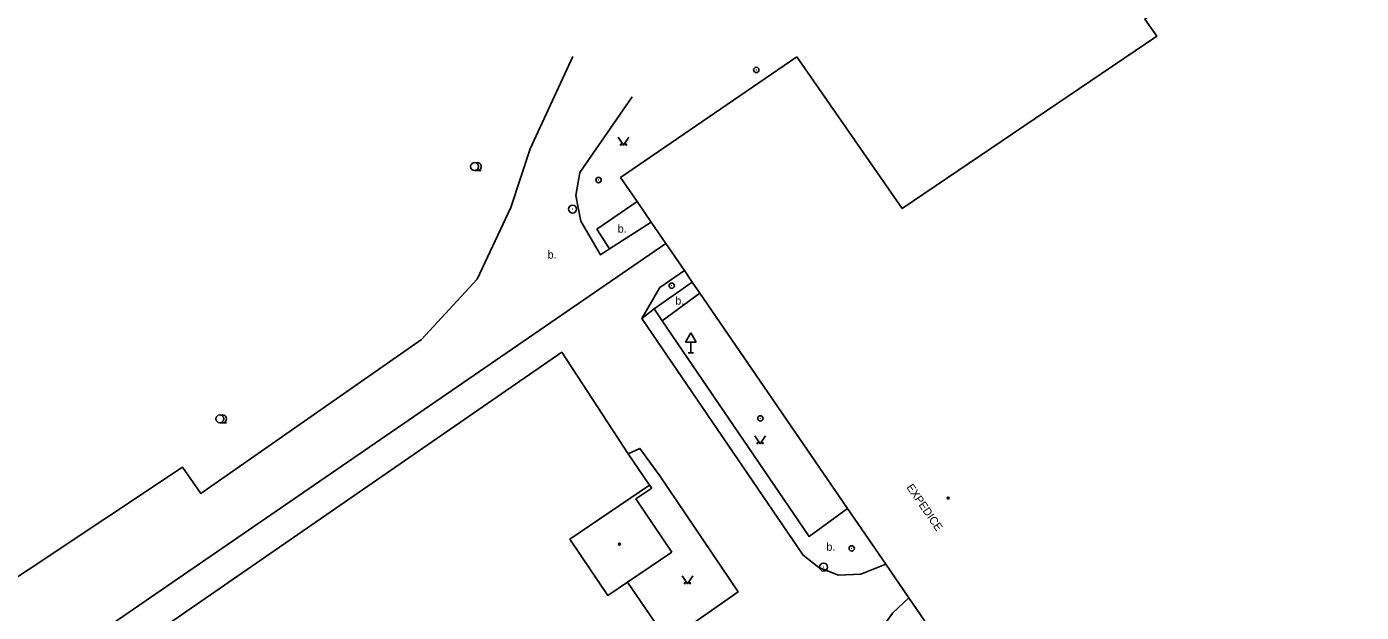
# Model space of a CAD drawing. Extents: x -545714 to -535419, y -1201788 to -1194297.
# Drawn here: x -545279.7 to -545154.6, y -1194807.5 to -1194752.6 of the extents above; entities that cross this region are included whole.
import ezdxf

# ---------------------------------------------------------------- set-up
doc = ezdxf.new("R2010")
doc.units = 0
for name, color, linetype in [('Vrstva 1', 7, 'Continuous'), ('Vrstva 10', 7, 'Continuous'), ('Vrstva 11', 7, 'Continuous'), ('Vrstva 15', 7, 'Continuous'), ('Vrstva 3', 7, 'Continuous'), ('Vrstva 4', 7, 'Continuous'), ('Vrstva 5', 7, 'Continuous'), ('Vrstva 9', 7, 'Continuous')]:
    doc.layers.add(name, color=color, linetype=linetype)

msp = doc.modelspace()

# ---------------------------------------------------------------- linework, layer by layer
at = {"layer": 'Vrstva 1'}
for centre, radius in [((-545228.49, -1194769.7), 0.375), ((-545228.49, -1194769.7), 0.0005), ((-545204.97, -1194803.28), 0.375), ((-545204.97, -1194803.28), 0.0005)]:
    msp.add_circle(centre, radius, dxfattribs=at)
at = {"layer": 'Vrstva 10'}
for p, q in [((-545217.41, -1194781.32), (-545217.91, -1194782.19)), ((-545217.41, -1194781.32), (-545216.91, -1194782.19)), ((-545217.91, -1194782.19), (-545216.91, -1194782.19)), ((-545217.41, -1194783.19), (-545217.41, -1194782.19)), ((-545217.66, -1194783.19), (-545217.16, -1194783.19))]:
    msp.add_line(p, q, dxfattribs=at)
for points in [[(-545219.75, -1194772.93), (-545277.34, -1194812.51), (-545286.35, -1194818.39), (-545298.69, -1194825.48), (-545311.57, -1194831.65), (-545328.37, -1194838.02), (-545342.45, -1194842.1)], [(-545216.56, -1194777.58), (-545220.1, -1194780.17), (-545220.84, -1194779.07), (-545217.27, -1194776.54)], [(-545221.27, -1194795.6), (-545223.27, -1194792.64), (-545229.51, -1194783.12), (-545266.38, -1194808.61), (-545303.95, -1194834.27), (-545301.94, -1194837.11)], [(-545199.15, -1194840.08), (-545223.35, -1194804.69)]]:
    msp.add_lwpolyline(points, dxfattribs=at)
for centre, radius in [((-545211.27, -1194756.65), 0.25), ((-545211.27, -1194756.65), 0.0005), ((-545226.06, -1194766.98), 0.25), ((-545226.06, -1194766.98), 0.0005), ((-545219.2, -1194776.89), 0.25), ((-545219.2, -1194776.89), 0.0005), ((-545210.89, -1194789.33), 0.25), ((-545210.89, -1194789.33), 0.0005), ((-545202.33, -1194801.52), 0.25), ((-545202.33, -1194801.52), 0.0005)]:
    msp.add_circle(centre, radius, dxfattribs=at)
at = {"layer": 'Vrstva 11'}
for points in [[(-545232.48, -1194764.06), (-545228.47, -1194755.38)], [(-545222.92, -1194759.17), (-545227.82, -1194766.27), (-545228.2, -1194768.42), (-545227.71, -1194770.84), (-545225.88, -1194773.98), (-545225.04, -1194773.44), (-545221.12, -1194770.93)], [(-545294.04, -1194813.16), (-545265.06, -1194793.9), (-545263.35, -1194796.36), (-545242.67, -1194781.94), (-545237.45, -1194776.27), (-545234.28, -1194769.55), (-545232.48, -1194764.06)], [(-545222.44, -1194769), (-545226.23, -1194771.59)], [(-545225.04, -1194773.44), (-545226.23, -1194771.59)], [(-545218.01, -1194775.46), (-545220.31, -1194777.04)], [(-545220.31, -1194777.04), (-545222, -1194779.96), (-545206.89, -1194802.17), (-545205.4, -1194803.31), (-545203.56, -1194804.02), (-545201.48, -1194803.93), (-545199.14, -1194802.99)], [(-545222, -1194779.96), (-545220.84, -1194779.07)], [(-545220.1, -1194780.17), (-545206.33, -1194800.4), (-545202.71, -1194797.78)], [(-545199.26, -1194838.53), (-545218.99, -1194809.8), (-545212.98, -1194805.59), (-545220.33, -1194794.71), (-545222.18, -1194792.15), (-545223.27, -1194792.64)], [(-545196.97, -1194806.15), (-545198.51, -1194807.6), (-545199.47, -1194808.96), (-545199.75, -1194811.2), (-545199.03, -1194813.48), (-545178.86, -1194843.1), (-545175.81, -1194842.57), (-545164.95, -1194835.42), (-545163.84, -1194833.77), (-545163.52, -1194831.74), (-545164.19, -1194829.82), (-545170.36, -1194820.85)]]:
    msp.add_lwpolyline(points, dxfattribs=at)
at = {"layer": 'Vrstva 3'}
for p, q in [((-545237.68, -1194766.08), (-545237.06, -1194766.08)), ((-545261.56, -1194789.75), (-545260.94, -1194789.75))]:
    msp.add_line(p, q, dxfattribs=at)
for points in [[(-545224.21, -1194762.96), (-545223.71, -1194763.71), (-545223.21, -1194762.96)], [(-545211.41, -1194790.96), (-545210.91, -1194791.71), (-545210.41, -1194790.96)], [(-545218.22, -1194804.09), (-545217.72, -1194804.84), (-545217.22, -1194804.09)]]:
    msp.add_lwpolyline(points, dxfattribs=at)
for centre, radius in [((-545223.96, -1194763.66), 0.05), ((-545223.46, -1194763.66), 0.05), ((-545237.68, -1194765.71), 0.375), ((-545261.56, -1194789.37), 0.375), ((-545211.16, -1194791.66), 0.05), ((-545210.66, -1194791.66), 0.05), ((-545217.97, -1194804.79), 0.05), ((-545217.47, -1194804.79), 0.05)]:
    msp.add_circle(centre, radius, dxfattribs=at)
for centre in [(-545237.43, -1194765.71), (-545261.31, -1194789.37)]:
    msp.add_arc(centre, 0.375, 249.4944, 109.0474, dxfattribs=at)
at = {"layer": 'Vrstva 4'}
for points in [[(-545207.47, -1194755.41), (-545223.99, -1194766.74), (-545222.44, -1194769), (-545221.12, -1194770.93), (-545219.75, -1194772.93), (-545218.01, -1194775.46), (-545217.27, -1194776.54), (-545216.56, -1194777.58), (-545202.71, -1194797.78), (-545199.14, -1194802.99), (-545196.97, -1194806.15), (-545181.61, -1194828.56), (-545179.83, -1194827.34), (-545178.41, -1194826.36), (-545170.36, -1194820.85), (-545167.07, -1194818.59), (-545161.65, -1194814.88), (-545159.32, -1194813.24), (-545154.36, -1194809.81), (-545125.58, -1194790.15)], [(-545228.76, -1194800.64), (-545221.27, -1194795.6), (-545221.06, -1194795.87)], [(-545222.57, -1194796.88), (-545221.06, -1194795.87)], [(-545222.57, -1194796.88), (-545219.2, -1194801.89)], [(-545219.2, -1194801.89), (-545223.35, -1194804.69), (-545225.2, -1194805.93), (-545228.76, -1194800.64)]]:
    msp.add_lwpolyline(points, dxfattribs=at)
at = {"layer": 'Vrstva 5'}
msp.add_lwpolyline([(-545081.5, -1194698.6), (-545086.75, -1194690.82), (-545093.63, -1194695.56), (-545095.62, -1194692.68), (-545120.66, -1194709.93), (-545113.45, -1194720.39), (-545116.6, -1194722.56), (-545121.94, -1194714.81), (-545147.2, -1194732.22), (-545146.78, -1194732.77), (-545174.84, -1194751.88), (-545173.74, -1194753.49), (-545197.59, -1194769.65), (-545207.47, -1194755.41)], dxfattribs=at)
at = {"layer": 'Vrstva 9'}
for centre in [(-545193.28, -1194796.8), (-545224.1, -1194801.12)]:
    msp.add_circle(centre, 0.0875, dxfattribs=at)

# ---------------------------------------------------------------- texts
at = {"layer": 'Vrstva 15'}
for p in [(-545224.26, -1194771.91), (-545230.83, -1194774.34), (-545218.86, -1194778.66), (-545204.7, -1194801.74)]:
    msp.add_text('b.', height=0.75, dxfattribs=at).set_placement(p)
msp.add_text('EXPEDICE', height=0.75, rotation=304.45, dxfattribs=at).set_placement((-545197.23, -1194795.79))

doc.saveas('drawing.dxf')
